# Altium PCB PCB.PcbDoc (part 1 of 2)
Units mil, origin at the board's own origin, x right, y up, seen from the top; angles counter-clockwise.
Board outline 3920 x 1470 mil, 2 copper layers (Top Layer, Bottom Layer), stack 60.433 mil thick; 97 components, 79 nets, 353 pads, 374 vias.
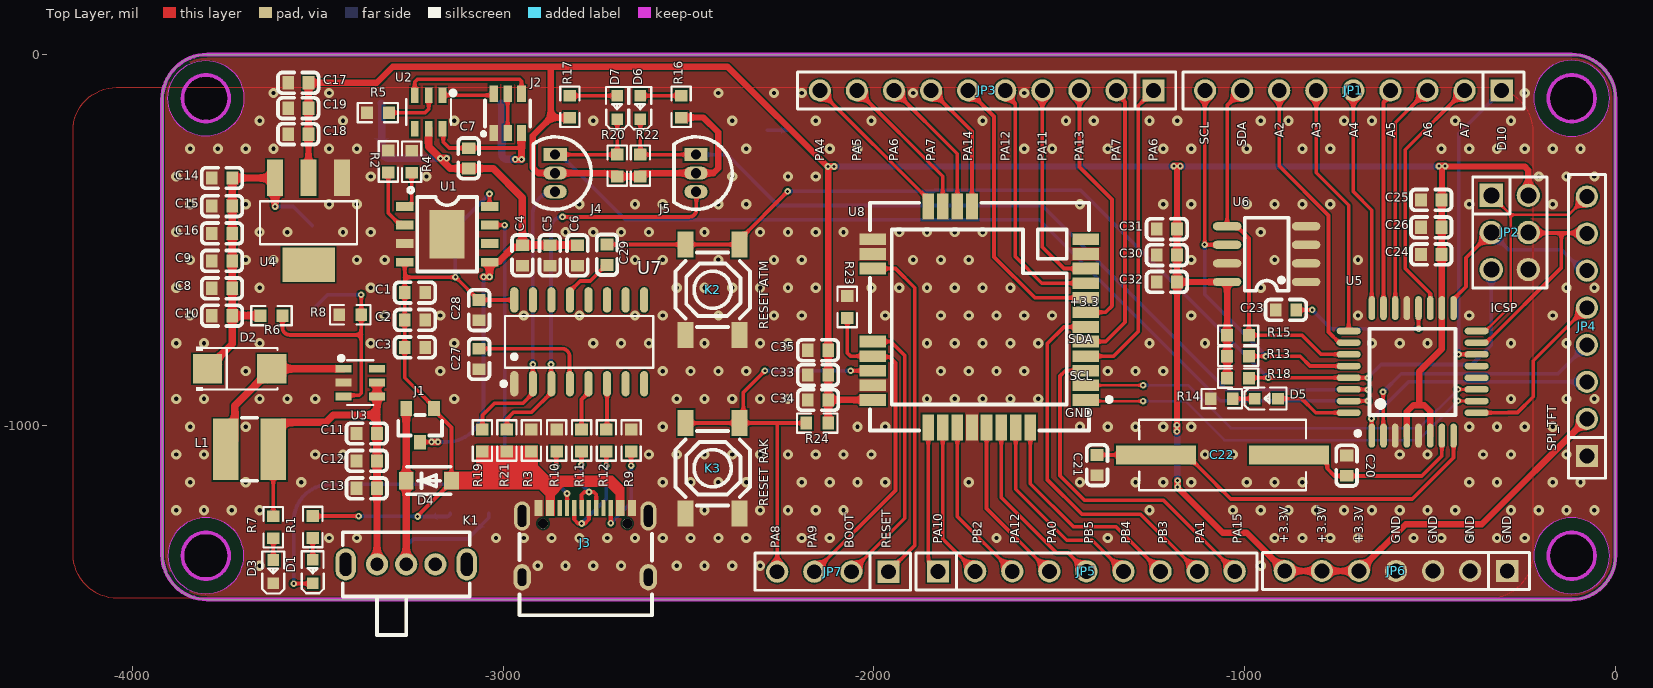
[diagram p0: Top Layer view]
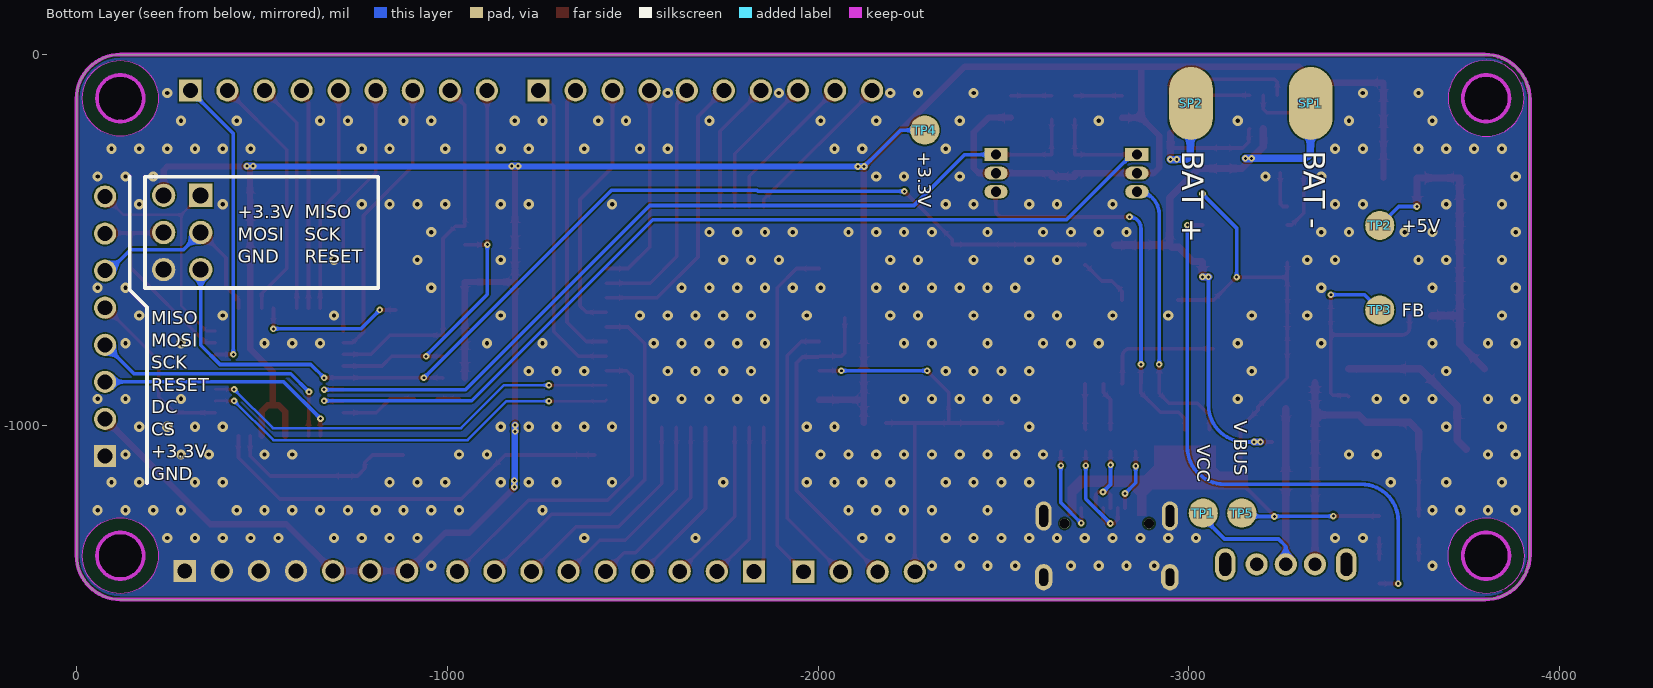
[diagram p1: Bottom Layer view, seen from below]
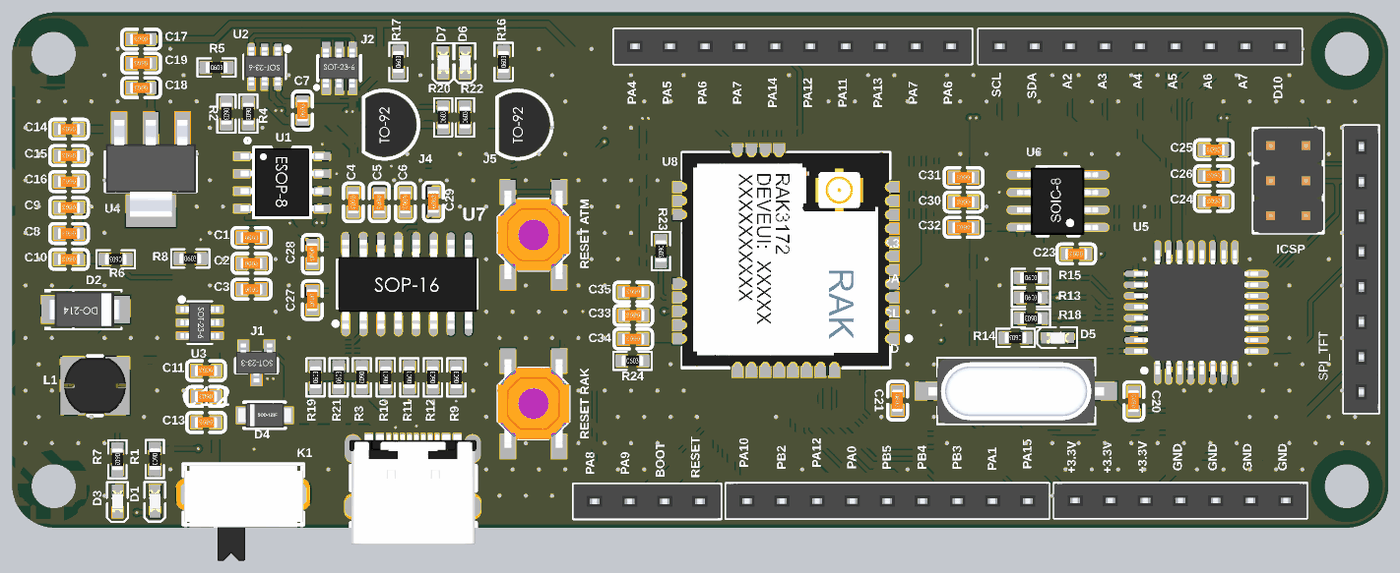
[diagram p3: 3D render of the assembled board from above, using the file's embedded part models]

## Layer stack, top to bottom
Top Solder: solder mask 0.5, Solder Resist, Dk 3.8
Top Layer: signal copper 1.378
Dielectric 1: prepreg 7.874, 7628, Dk 4.6
Core: core 41.929, FR-4, Dk 4.5
Dielectric 2: prepreg 7.874, 7628, Dk 4.6
Bottom Layer: signal copper 1.378
Bottom Solder: solder mask 0.5, Solder Resist, Dk 3.8

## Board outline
-3920,-1348.7 ccw(c-3798.7,-1348.7) -3798.7,-1470 -118.5,-1470 ccw(c-118.5,-1351.5) 0,-1351.5 0,-118.5 ccw(c-118.5,-118.5) -118.5,0 -3798.44,0 ccw(c-3798.44,-121.56) -3920,-121.56
cut-out: -181.1,-118.11 ccw(c-118.11,-118.11) -118.11,-181.1 ccw(c-118.11,-118.11) -55.12,-118.11 ccw(c-118.11,-118.11) -118.11,-55.12 ccw(c-118.11,-118.11)
cut-out: -3801.89,-181.1 cw(c-3801.89,-118.11) -3864.88,-118.11 cw(c-3801.89,-118.11) -3801.89,-55.12 cw(c-3801.89,-118.11) -3738.9,-118.11 cw(c-3801.89,-118.11)
cut-out: -3864.88,-1351.89 ccw(c-3801.89,-1351.89) -3801.89,-1414.88 ccw(c-3801.89,-1351.89) -3738.9,-1351.89 ccw(c-3801.89,-1351.89) -3801.89,-1288.9 ccw(c-3801.89,-1351.89)
cut-out: -181.1,-1351.89 ccw(c-118.11,-1351.89) -118.11,-1414.88 ccw(c-118.11,-1351.89) -55.12,-1351.89 ccw(c-118.11,-1351.89) -118.11,-1288.9 ccw(c-118.11,-1351.89)

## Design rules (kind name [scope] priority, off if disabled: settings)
BoardOutlineClearance [All] p1: gap=7.87 ignorepadtopadclearanceinfootprint=FALSE
Clearance Clearance_1 [InNet('No Net') vs InNet('No Net')] p1: gap=10 ignorepadtopadclearanceinfootprint=FALSE
Clearance [All] p2: gap=4 ignorepadtopadclearanceinfootprint=FALSE except(5: Arc-Via Track-Via SMDPad-Via THPad-Via Via-Via Via-Fill Via-Poly Via-Region)
ComponentClearance [All] p1: gap=4 collisioncheckmode=3 verticalgap=4 showdistances=TRUE
DiffPairsRouting [All] p1: maxlimit=4 minlimit=4 mostfreqgap=4 toplayer_minwidth=4 toplayer_maxwidth=71497.94 toplayer_prefwidth=4 bottomlayer_minwidth=4 bottomlayer_maxwidth=71497.94 bottomlayer_prefwidth=4 maxuncoupledlength=500
Height [All] p1: minheight=0 maxheight=71497.94 prefheight=500
HoleSize [All] p1: absolutevalues=TRUE maxlimit=248.03 minlimit=7.87 maxpercent=80.000 minpercent=20.000
HoleToHoleClearance [All] p1: gap=9.84 allowstackedmicrovias=FALSE
MinimumAnnularRing [All] p1: minimumring=3
MinimumSolderMaskSliver [All] p1: minsoldermaskwidth=0
PlaneClearance [All] p1: clearance=4
PlaneConnect PlaneConnectPowerPads [InPadClass('PowerPads')] p1: planeconnectstyle=Direct reliefexpansion=20 reliefentries=4 reliefconductorwidth=10 reliefairgap=10
PlaneConnect [All] p2: pad.planeconnectstyle=Relief pad.reliefexpansion=11.81 pad.reliefentries=4 pad.reliefconductorwidth=4 pad.reliefairgap=4 via.planeconnectstyle=Direct via.reliefexpansion=11.81 via.reliefentries=4 via.reliefconductorwidth=5 via.reliefairgap=5
PolygonConnect PolygonConnectPowerPads [All vs (InPadClass('PowerPads'))] p1: connectstyle=Direct reliefconductorwidth=10 reliefentries=4 polygonreliefangle="90 Angle" airgapwidth=10
PolygonConnect [All] p2: connectstyle=Direct reliefconductorwidth=4 reliefentries=4 polygonreliefangle="90 Angle" airgapwidth=4
RoutingVias [All] p1: holewidth=7.87 width=17.72 viastyle="Through Hole" minholewidth=7.87 minwidth=17.72 maxholewidth=248.03 maxwidth=257.87
SilkToSilkClearance [All] p1: silktosilkclearance=0
SilkToSolderMaskClearance [IsPad] p1: minsilkscreentomaskgap=4 clearancetoexposedcopper=TRUE
SolderMaskExpansion [All] p1: expansion=2.95 istentingtop=FALSE
Width [All] p1: maxlimit=71497.94 minlimit=4 preferedwidth=4
20 further rules are at their usual default settings.

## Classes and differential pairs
component class "Voltage Source": C1 C2 C3 C4 C5 C6 C7 C8 C9 C10 C11 C12 C13 C14 C15 C16 C17 C18 C19 D1 D2 D3 D4 J1 J2 J3 K1 L1 R1 R2 R3 R4 R5 R6 R7 R8 R9 R10 R11 R12 SP1 SP2 TP1 TP2 TP3 TP4 TP5 U1 U2 U3 U4
component class Peripheral: C27 C28 C29 C30 C31 C32 C33 C34 C35 J4 J5 K3 R19 R20 R21 R22 R23 R24 Reset_U4 U6 U7 U8
component class "Micro Controller": C20 C21 C22 C23 C24 C25 C26 D5 D6 D7 K2 R13 R14 R15 R16 R17 R18 Reset_U4 U5
component class Connector: JP1 JP2 JP3 JP4 JP5 JP6 JP7
differential pair D: +D_P -D_N

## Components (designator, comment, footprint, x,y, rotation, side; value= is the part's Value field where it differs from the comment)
C1 "100nF" C0603 -3238.19,-642.03 r0 top
C2 "10uF" C0603 -3238.19,-715.94 r0 top
C3 "22uF" C0603 -3238.19,-789.85 r0 top
C4 "100nF" C0603 -2948.12,-541.81 r270 top
C5 "10uF" C0603 -2874.21,-541.81 r270 top
C6 "22uF" C0603 -2800.07,-541.81 r270 top
C7 "100nF" C0603 -3093,-280 r90 top
C8 "100nF" C0603 -3758.31,-630.54 r180 top
C9 "10uF" C0603 -3758.31,-556.63 r180 top
C10 "22uF" C0603 -3758.31,-704.46 r180 top
C11 "100nF" C0603 -3367.87,-1022.15 r180 top
C12 "10uF" C0603 -3367.87,-1096.06 r180 top
C13 "22uF" C0603 -3367.87,-1169.97 r180 top
C14 "100nF" C0603 -3758.31,-333.07 r180 top
C15 "10uF" C0603 -3758.31,-408.76 r180 top
C16 "22uF" C0603 -3758.31,-482.67 r180 top
C17 "100nF" C0603 -3552.56,-76.27 r180 top
C18 "10uF" C0603 -3552.56,-214.94 r180 top
C19 "22uF" C0603 -3552.56,-144.94 r180 top
C20 "12pF" C0603 -725,-1109 r90 top
C21 "12pF" C0603 -1398,-1107.56 r270 top
C22 "X49SM16MSD2SC" X49SM16MSD2SC -1060,-1080 r0 top
C23 "100nF" C0603 -889,-689 r180 top
C24 "100nF" C0603 -497,-539.25 r180 top
C25 "10uF" C0603 -497,-392 r180 top
C26 "22uF" C0603 -497,-466 r180 top
C27 "100nF" C0603 -3065,-821 r270 top
C28 "100nF" C0603 -3065,-689.47 r270 top
C29 "100nF" C0603 -2720,-540 r90 top
C30 "100nF" C0603 -1210,-541 r180 top
C31 "10uF" C0603 -1210,-471 r180 top
C32 "22uF" C0603 -1210,-613.41 r180 top
C33 "100nF" C0603 -2150.81,-864.55 r180 top
C34 "10uF" C0603 -2151,-931.66 r180 top
C35 "22uF" C0603 -2151,-797.66 r180 top
D1 "RED" LED0603 -3513.54,-1394.46 r90 top
D2 "SS34" SS34 -3711,-847.6 r0 top
D3 "YELLOW" LED0603 -3620,-1395 r90 top
D4 "SOD4007" SOD4007 -3200.55,-1149.37 r0 top
D5 "YELLOW" LED0603 -941.73,-928.25 r0 top
D6 "YELLOW" LED0603 -2630.14,-142.82 r90 top
D7 "YELLOW" LED0603 -2692.55,-142.82 r90 top
J1 "AO3401A" AO3401A -3224.17,-1000 r90 top
J2 "FS8205A" FS8205A -2988,-159 r270 top
J3 "TYPE-C 16PIN 2MD(073)" TYPE_C_FAMALE -2778.78,-1316.37 r0 top
J4 "2N7000" 2N7000 -2860,-320 r270 top
J5 "2N7000" 2N7000 -2480,-320 r270 top
JP1 "JP 1x9 2.54" "JP 1x9 CT" -707,-97 r180 top
JP2 "Header" "JP 2x3 DT" -285,-480 r270 top
JP3 "Header" "JP 1x10 CT" -1245.91,-97.02 r180 top
JP4 "JP 1x8 2.54" "JP 1x8 CT" -77,-1083 r90 top
JP5 "JP 1x9 2.54" "JP 1x9 CT" -1427,-1394 r0 top
JP6 "JP 1x7 2.54" "JP 1x7 CT" -292,-1393 r180 top
JP7 "JP 1x4 2.54" "JP 1x4 CT" -1961,-1395 r180 top
K1 "SK12D07VG4" SK12D07VG4 -3261.58,-1375 r0 top
K2 "TS-1140SP-4x4x1.5-260" 4x4x1.5 -2435,-634.49 r90 top
K3 "TS-1140SP-4x4x1.5-260" 4x4x1.5 -2435,-1116.05 r90 top
L1 "220uH" CD43 -3684.12,-1065 r270 top
R1 "1kΩ" R0603 -3513.68,-1274.46 r270 top
R2 "2kΩ" R0603 -3309.81,-288.78 r270 top
R3 "10kΩ" R0603 -2924,-1041 r270 top
R4 "1kΩ" R0603 -3247,-289 r270 top
R5 "1kΩ" R0603 -3338,-157 r0 top
R6 "5k1" R0603 -3625,-704.46 r180 top
R7 "1kΩ" R0603 -3620.14,-1275 r270 top
R8 "680" R0603 -3412.66,-702 r0 top
R9 "5k1Ω" R0603 -2654.87,-1041.22 r90 top
R10 "5k1Ω" R0603 -2855.98,-1041.22 r90 top
R11 "0Ω" R0603 -2788.73,-1041.22 r90 top
R12 "0Ω" R0603 -2721.8,-1041.22 r90 top
R13 "4k7Ω" R0603 -1017.84,-813.78 r0 top
R14 "1kΩ" R0603 -1061.73,-928.25 r180 top
R15 "4k7Ω" R0603 -1017.84,-757.23 r0 top
R16 "1kΩ" R0603 -2520,-141 r90 top
R17 "1kΩ" R0603 -2820,-141 r90 top
R18 "10kΩ" R0603 -1017.84,-872.78 r180 top
R19 "10kΩ" R0603 -3056,-1041 r90 top
R20 "10kΩ" R0603 -2692.41,-299.66 r90 top
R21 "10kΩ" R0603 -2990,-1041 r90 top
R22 "10kΩ" R0603 -2630,-299.66 r90 top
R23 "10kΩ" R0603 -2072,-681 r270 top
R24 "10kΩ" R0603 -2153.1,-994 r0 top
SP1 "BAT+" SP -3329,-132 r0 top
SP2 "BAT-" SP -3006,-132 r180 top
TP1 "TP" TP -3039,-1237 r0 top
TP2 "TP" TP -3515,-461 r0 top
TP3 "TP" TP -3515,-689 r0 top
TP4 "TP" TP -2288,-204 r0 top
TP5 "TP" TP -3143,-1237 r0 top
U1 "TP4056" TP4056 -3151.25,-485 r270 top
U2 "DW01A" DW01A -3201,-155 r180 top
U3 "MT3608" MT3608 -3385.55,-885 r270 top
U4 "LM1117S-3.3" AMS1117-3.3 -3525,-450 r90 top
U5 "ATMEGA328-AU" ATMEGA328-AU -547,-856 r0 top
U6 "AT24C02C-SSHM-T" AT24C02C-SSHM-T -941,-538.41 r90 top
U7 "CH340C" CH340C -2795,-775 r0 top
U8 "RAK3172-9-SM-I" RAK3172-9-SM-I -1716,-708 r180 top

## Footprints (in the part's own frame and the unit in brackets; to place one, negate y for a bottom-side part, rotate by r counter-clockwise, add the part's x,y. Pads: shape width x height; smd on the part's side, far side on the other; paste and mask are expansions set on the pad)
2N7000 [mm]
  rect 0.9x1.6 hole 0.7 paste-2539.97 mask+0.051: 1(-1.27,0)
  oval 0.9x1.6 hole 0.7 paste-2539.97 mask+0.051: 2(0,0) 3(1.27,0)
  silkscreen extent -2.48,-1.5 2.48,2.48, body extent -2.3,-1.3 2.3,2.3, height 5.6
4x4x1.5 [mm]
  rect 1.8x1.1 smd paste+0 mask+0.051: 1(-3.1,1.85) 2(3.1,1.85) 3(-3.1,-1.85) 4(3.1,-1.85)
  silkscreen extent -2.55,-2.55 2.55,2.55, body extent -3.2,-2.6 3.2,2.6, height 1.5
AMS1117-3.3 [mm]
  rect 2.5x1.1 smd paste+0 mask+0.051: 1(2.97,-2.3) 2(2.97,0) 3(2.97,2.3)
  rect 2.34x3.6 smd paste+0 mask+0.051: 4(-2.97,0)
  silkscreen extent -1.57,-3.33 1.37,3.33, body extent -3.37,-3.25 3.63,3.25, height 1.8
AO3401A [mm]
  rect 1x0.8 smd paste+0 mask+0.051: 1(1.15,-0.95) 2(1.15,0.95) 3(-1.15,0)
  silkscreen extent -0.7,-1.5 0.7,1.5, body extent -1.4,-1.45 1.4,1.45, height 1.26
AT24C02C-SSHM-T [mil]
  oval 22.38x76.78 smd paste+0 mask+2: 1(-75,-106.5) 2(-25,-106.5) 3(25,-106.5) 4(75,-106.5) 5(75,106.5) 6(25,106.5) 7(-25,106.5) 8(-75,106.5)
  silkscreen extent -98,-59 98,59, body extent -96,-115 96,117, height 60
ATMEGA328-AU [mm]
  oval 0.45x1.65 smd paste+0 mask+0.051: 1(-2.8,-4.369) 2(-2,-4.369) 3(-1.2,-4.369) 4(-0.4,-4.369) 5(0.4,-4.369) 6(1.2,-4.369) 7(2,-4.369) 8(2.8,-4.369) 17(2.8,4.369) 18(2,4.369) 19(1.2,4.369) 20(0.4,4.369) 21(-0.4,4.369) 22(-1.2,4.369) 23(-2,4.369) 24(-2.8,4.369)
  oval 1.65x0.45 smd paste+0 mask+0.051: 9(4.382,-2.8) 10(4.382,-2) 11(4.382,-1.2) 12(4.382,-0.4) 13(4.382,0.4) 14(4.382,1.2) 15(4.382,2) 16(4.382,2.8) 25(-4.381,2.8) 26(-4.381,2) 27(-4.381,1.2) 28(-4.381,0.4) 29(-4.381,-0.4) 30(-4.381,-1.2) 31(-4.381,-2) 32(-4.381,-2.8)
  silkscreen extent -3.91,-4.36 2.94,2.95, body extent -4.5,-4.5 4.5,4.5, height 1.05
C0603 [mm]
  rect 0.8x0.9 smd: 1(-0.7,0) 2(0.7,0)
  silkscreen extent -1.39,-0.71 1.39,0.71, body extent -0.8,-0.4 0.8,0.4, height 0.4
CD43 [mm]
  rect 4.2x1.75 smd paste+0 mask+0.051: 1(0,1.625) 2(0,-1.625)
  silkscreen extent -2.16,-0.52 2.16,0.52, body extent -2,-2.25 2,2.25, height 3.22
CH340C [mm]
  oval 0.56x1.745 smd paste+0 mask+0.051: 1(-4.445,-2.873) 2(-3.175,-2.873) 3(-1.905,-2.873) 4(-0.635,-2.873) 5(0.635,-2.873) 6(1.905,-2.873) 7(3.175,-2.873) 8(4.445,-2.873) 9(4.445,2.873) 10(3.175,2.873) 11(1.905,2.873) 12(0.635,2.873) 13(-0.635,2.873) 14(-1.905,2.873) 15(-3.175,2.873) 16(-4.445,2.873)
  silkscreen extent -5.33,-3.02 5.08,1.77, body extent -4.95,-3.26 5.05,3.2, height 1.92
DW01A [mm]
  rect 0.532x1.072 smd paste+0 mask+0.051: 1(-0.95,-1.149) 2(0,-1.149) 3(0.95,-1.149) 4(0.95,1.149) 5(0,1.149) 6(-0.95,1.149)
  silkscreen extent -1.82,-1.45 1.54,0.89, body extent -1.45,-1.43 1.45,1.37, height 1.46
FS8205A [mm]
  rect 1.1x0.6 smd paste+0 mask+0.051: 1(1.35,-0.95) 2(1.35,0) 3(1.35,0.95) 4(-1.35,0.95) 5(-1.35,0) 6(-1.35,-0.95)
  silkscreen extent -0.9,-1.78 1.52,1.55, body extent -1.4,-1.48 1.4,1.42, height 1.46
"JP 1x4 CT" [mm]
  rect 1.52x1.52 hole 1.02: 1(0,0)
  round 1.52 hole 1.02: 2(2.54,0) 3(5.08,0) 4(7.62,0)
  silkscreen extent -1.52,-1.27 9.14,1.27, body extent -1.52,-1.25 9.14,1.25, height 8.51
"JP 1x7 CT" [mm] "7 row, straight, gold plating"
  rect 1.52x1.52 hole 1.02: 1(0,0)
  round 1.52 hole 1.02: 2(2.54,0) 3(5.08,0) 4(7.62,0) 5(10.16,0) 6(12.7,0) 7(15.24,0)
  silkscreen extent -1.52,-1.27 16.76,1.27, body extent -1.52,-1.25 16.76,1.25, height 8.51
"JP 1x8 CT" [mm] "8 row, straight, gold plating"
  rect 1.52x1.52 hole 1.02: 1(0,0)
  round 1.52 hole 1.02: 2(2.54,0) 3(5.08,0) 4(7.62,0) 5(10.16,0) 6(12.7,0) 7(15.24,0) 8(17.78,0)
  silkscreen extent -1.52,-1.27 19.3,1.27, body extent -1.52,-1.25 19.3,1.25, height 8.51
"JP 1x9 CT" [mm] "9 row, straight, gold plating"
  rect 1.52x1.52 hole 1.02: 1(-10.16,0)
  round 1.52 hole 1.02: 2(-7.62,0) 3(-5.08,0) 4(-2.54,0) 5(0,0) 6(2.54,0) 7(5.08,0) 8(7.62,0) 9(10.16,0)
  silkscreen extent -11.68,-1.27 11.68,1.27, body extent -11.68,-1.25 11.68,1.25, height 8.51
"JP 1x10 CT" [mm] "10 row, straight, gold plating"
  rect 1.52x1.52 hole 1.02: 1(0,0)
  round 1.52 hole 1.02: 2(2.54,0) 3(5.08,0) 4(7.62,0) 5(10.16,0) 6(12.7,0) 7(15.24,0) 8(17.78,0) 9(20.32,0) 10(22.86,0)
  silkscreen extent -1.52,-1.27 24.38,1.27, body extent -1.52,-1.25 24.38,1.25, height 8.51
"JP 2x3 DT" [mm]
  rect 1.6x1.6 hole 1.1: 1(-2.54,-1.27)
  round 1.6 hole 1.1: 2(0,-1.27) 3(2.54,-1.27) 4(2.54,1.27) 5(0,1.27) 6(-2.54,1.27)
  silkscreen extent -3.81,-2.54 3.81,2.54, body extent -3.81,-2.54 3.81,2.54, height 8.55
LED0603 [mm]
  rect 0.8x0.8 smd paste+0 mask+0.051: 1(-0.799,-0.004) 2(0.799,0.004)
  silkscreen extent -1.49,-0.75 1.39,0.76, body extent -0.8,-0.42 0.8,0.38, height 0.7
MT3608 [mm]
  rect 0.532x1.072 smd paste+0 mask+0.051: 1(-0.95,-1.149) 2(0,-1.149) 3(0.95,-1.149) 4(0.95,1.149) 5(0,1.149) 6(-0.95,1.149)
  silkscreen extent -1.82,-1.45 1.54,0.89, body extent -1.45,-1.4 1.45,1.4, height 1.46
R0603 [mil]
  rect 31.75x34.02 smd paste-3937.01 mask+2: 1(-29.66,0) 2(29.66,0)
  silkscreen extent -55,-26 55,26, body extent -31,-16 31,16, height 18
RAK3172-9-SM-I [mm]
  rect 1.8x0.8 smd paste+0 mask+0.051: 1(-7.287,5.68) 2(-7.287,4.68) 3(-7.287,3.68) 4(-7.287,2.68) 5(-7.287,1.68) 6(-7.287,0.68) 7(-7.287,-0.32) 8(-7.287,-1.32) 9(-7.287,-2.32) 10(-7.287,-3.32) 11(-7.287,-4.32) 12(-7.287,-5.32) 17(7.287,-5.32) 18(7.287,-4.32) 19(7.287,-3.32) 20(7.287,1.68) 21(7.287,2.68) 22(7.287,3.68) 23(7.287,4.68) 24(7.287,5.68)
  rect 0.8x1.8 smd paste+0 mask+0.051: 13(0.5,-7.569) 14(1.5,-7.569) 15(2.5,-7.569) 16(3.5,-7.569) 25(3.5,7.569) 26(2.5,7.569) 27(1.5,7.569) 28(0.5,7.569) 29(-0.5,7.569) 30(-1.5,7.569) 31(-2.5,7.569) 32(-3.5,7.569)
  silkscreen extent -9.05,-7.82 7.49,7.78, body extent -7.5,-7.82 7.49,7.67, height 3.51
SK12D07VG4 [mil]
  round 60 hole 36 paste-99999 mask+1.97: 1(-78.74,0) 2(0,0) 3(78.74,0)
  oval 55.12x86.61 hole 31.5 slot 62.99 at 90 deg paste-99999 mask+1.97: 4(163.39,0) 5(-163.39,0)
  silkscreen extent -171,-191 171,87, body extent -169,-190 170,83, height 188
SOD4007 [mm]
  rect 1x1.2 smd paste+0 mask+0.051: 1(-1.55,0) 2(1.55,0)
  silkscreen extent -1.52,-0.93 1.49,0.95, body extent -1.9,-0.9 1.9,0.9, height 1.02
SP [mm]
  oval 3x5 smd far side paste+0 mask+0.051: 1(0,0)
SS34 [mm]
  rect 2x2 smd paste+0 mask+0.051: 1(-2.2,0) 2(2.2,0)
  silkscreen extent -2.98,-1.5 2.6,1.5, body extent -2.65,-1.29 2.49,1.27, height 2.63
TP [mm]
  round 2 smd far side paste+0 mask+0.051: 1(0,0)
TP4056 [mm]
  rect 0.6x1.2 smd paste+0 mask+0.051: 1(-1.905,-2.908) 2(-0.635,-2.908) 3(0.635,-2.908) 4(1.905,-2.908) 5(1.905,2.908) 6(0.635,2.908) 7(-0.635,2.908) 8(-1.905,2.908)
  rect 3.3x2.4 smd paste+0 mask+0.051: 9(0,0)
  silkscreen extent -3.2,-2.67 2.55,2.05, body extent -2.46,-3 2.44,3, height 1.76
TYPE_C_FAMALE [mm]
  rect 0.55x1.1 smd paste-100 mask+0.05: 1(-3.2,2.375) 2(-2.4,2.375) 11(2.4,2.375) 12(3.2,2.375)
  rect 0.3x1.1 smd paste-100 mask+0.05: 3(-1.75,2.375) 4(-1.25,2.375) 5(-0.75,2.375) 6(-0.25,2.375) 7(0.25,2.375) 8(0.75,2.375) 9(1.25,2.375) 10(1.75,2.375)
  oval 1.2x1.8 hole 0.6 slot 1.2 at 90 deg paste-2539.97 mask+0.05: 13(-4.325,-2.375) 14(4.325,-2.375)
  oval 1.1x2 hole 0.6 slot 1.5 at 90 deg paste-2539.97 mask+0.05: 13(-4.325,1.825) 14(4.325,1.825)
  round 0.7 hole 0.7 unplated paste-2539.97: ""(-2.89,1.305) ""(2.89,1.305)
  silkscreen extent -4.5,-4.97 4.57,0.6, body extent -4.57,-5.09 4.63,2.86, height 3.21
X49SM16MSD2SC [mm]
  rect 5.5x1.3 smd paste+0 mask+0.051: 1(-4.553,0) 2(4.553,0)
  silkscreen extent -5.71,-2.41 5.72,2.41, body extent -6.35,-2.38 6.35,2.32, height 4.2

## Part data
C1 C4 C7 C8 C11 C14 C17 C23 C24 C27 C28 C29 C30 C33: library part C0603_100nF_±1%, "50V 10pF NP0 ±1% 0402 Multilayer Ceramic Capacitors MLCC - SMD/SMT ROHS", LCSC Part #=C513681, Manufacturer=YAGEO, Mfr. Part #=CC0402FRNPO9BN100, Package=0603, Tolerance=±1%, Voltage Rating=50V
C2 C5 C9 C12 C15 C18 C25 C31 C34: library part C0603_10uF_±1%, "50V 10pF NP0 ±1% 0402 Multilayer Ceramic Capacitors MLCC - SMD/SMT ROHS", LCSC Part #=C513681, Manufacturer=YAGEO, Mfr. Part #=CC0402FRNPO9BN100, Package=0603, Tolerance=±1%, Voltage Rating=50V
C3 C6 C10 C13 C16 C19 C26 C32 C35: library part C0603_22uF_±1%, "50V 10pF NP0 ±1% 0402 Multilayer Ceramic Capacitors MLCC - SMD/SMT ROHS", LCSC Part #=C513681, Manufacturer=YAGEO, Mfr. Part #=CC0402FRNPO9BN100, Package=0603, Tolerance=±1%, Voltage Rating=50V
C20 C21: library part C0603_12pF_±1%, "50V 10pF NP0 ±1% 0402 Multilayer Ceramic Capacitors MLCC - SMD/SMT ROHS", LCSC Part #=C513681, Manufacturer=YAGEO, Mfr. Part #=CC0402FRNPO9BN100, Package=0603, Tolerance=±1%, Voltage Rating=50V
C22: "16MHz Crystal Oscillator 20pF ±20ppm ±30ppm HC-49S-SMD Crystals ROHS", LCSC Part #=C12676, Load Capacitance=20pF, Manufacturer="YXC Crystal Oscillators", Package=HC-49S-SMD
D1: library part D0603_RED, "25mcd~40mcd Water Clear -40℃~+85℃ 624nm Red 120° 60mW 0402 LED Indication - Discrete ROHS", LCSC Part #=C965793, Manufacturer=XINGLIGHT, Mfr. Part #=XL-1005UGC, Package=0603, Power(Watts)=60mW, Voltage - Forward(Vf)=3V
D2: "40V Independent 3A 550mV@3A SMA(DO-214AC) Schottky Diodes ROHS", Current - Rectified=3A, LCSC Part #=C8678, Manufacturer="MDD(Microdiode Semiconductor)", Package=SMA(DO-214AC), Voltage - DC Reverse(Vr)=40V
D3 D5 D6 D7: library part D0603_YELLOW, "25mcd~40mcd Water Clear -40℃~+85℃ 624nm Red 120° 60mW 0402 LED Indication - Discrete ROHS", LCSC Part #=C965793, Manufacturer=XINGLIGHT, Mfr. Part #=XL-1005UGC, Package=0603, Power(Watts)=60mW, Voltage - Forward(Vf)=3V
D4: "1A Independent 1kV 1.1V@1A SOD-123FL Diodes - General Purpose ROHS", Current - Rectified=1A, LCSC Part #=C18124, Manufacturer="MDD(Microdiode Semiconductor)", Package=SOD-123FL, Voltage - DC Reverse(Vr)=1kV
J1: library part AO3401, "30V 4A 900mV@250uA 1 P-Channel SOT-23 MOSFETs ROHS", Current - Continuous Drain(Id)=4A, Drain to Source Voltage=30V, LCSC Part #=C15127, Manufacturer=AOS, Package=SOT-23
J2: "20V 9A 31.5mΩ@2.5V 1.5W 1.2V@250uA SOT-23-6 MOSFETs ROHS", Current - Continuous Drain(Id)=9A, Drain to Source Voltage=20V, LCSC Part #=C2830320, Manufacturer="TECH PUBLIC", Package=SOT-23-6
J3: library part TYPE_C_FAMALE_16PIN, "3A 1 Surface Mount, Right Angle 16P Female -25℃~+85℃ Type-C SMD USB Connectors ROHS", LCSC Part #=C2765186, Manufacturer="SHOU HAN", Package=SMD
J4 J5: "60V 200mA 400mW 5Ω@10V 3V@1mA 1 N-Channel TO-92-3L MOSFETs ROHS", Current - Continuous Drain(Id)=200mA, Drain to Source Voltage=60V, Gate Threshold Voltage (Vgs(th))=3V@1mA, LCSC Part #=C232838, Manufacturer=onsemi, Package=TO-92-3L
JP1 JP5: library part "JP 1x9 2.54 Cai Thang", "Cắm"
JP2: library part "JP 2x3 2.54 Duc Thang", "Cắm"
JP3: library part "JP 1x10 2.54 Cai Thang", "Cắm"
JP4: library part "JP 1x8 2.54 Cai Thang", "Cắm"
JP6: library part "JP 1x7 2.54 Cai Thang", "Cắm"
JP7: library part "JP 1x4 2.54 Cai Thang", "Cắm"
K1: "500mA SPDT 50V 5,000 Cycles Through Hole Slide Switches ROHS", LCSC Part #=C393937, Manufacturer="SHOU HAN", Package="Through Hole"
K2 K3: "SMD Tactile Switches ROHS", LCSC Part #=C49023394, Manufacturer=CAX, Package=SMD
L1: library part CD4-220UH, "360mA 220uH ±20% SMD,4.5x4x3.2mm Power Inductors ROHS", Current Rating=360mA, DC Resistance(DCR)=3.4Ω, LCSC Part #=C492283, Manufacturer=YJYCOIN, Mfr. Part #=CD43YP0403-221M, Package=SMD,4.5x4x3.2mm, Tolerance=±20%
R1 R4 R5 R7 R14 R16 R17: library part R0603_1kΩ_±1%, "62.5mW Thick Film Resistor 50V ±1% ±200ppm/℃ 10Ω 0402 Chip Resistor - Surface Mount ROHS", LCSC Part #=C138066, Manufacturer=YAGEO, Mfr. Part #=RC0402FR-0710RL, Package=0603, Tolerance=±1%
R2: library part R0603_2kΩ_±1%, "62.5mW Thick Film Resistor 50V ±1% ±200ppm/℃ 10Ω 0402 Chip Resistor - Surface Mount ROHS", LCSC Part #=C138066, Manufacturer=YAGEO, Mfr. Part #=RC0402FR-0710RL, Package=0603, Tolerance=±1%
R3 R18 R19 R20 R21 R22 R23 R24: library part R0603_10kΩ_±1%, "62.5mW Thick Film Resistor 50V ±1% ±200ppm/℃ 10Ω 0402 Chip Resistor - Surface Mount ROHS", LCSC Part #=C138066, Manufacturer=YAGEO, Mfr. Part #=RC0402FR-0710RL, Package=0603, Tolerance=±1%
R6: library part R0603_10kΩ_±1%, "62.5mW Thick Film Resistor 50V ±1% ±200ppm/℃ 10Ω 0402 Chip Resistor - Surface Mount ROHS", LCSC Part #=C138066, Manufacturer=YAGEO, Mfr. Part #=RC0402FR-0710RL, Package=0603, Resistance=10kΩ, Tolerance=±1%
R8: library part R0603_2kΩ_±1%, "62.5mW Thick Film Resistor 50V ±1% ±200ppm/℃ 10Ω 0402 Chip Resistor - Surface Mount ROHS", LCSC Part #=C138066, Manufacturer=YAGEO, Mfr. Part #=RC0402FR-0710RL, Package=0603, Resistance=2kΩ, Tolerance=±1%
R9 R10: library part R0603_5k1Ω_±1%, "100mW Thick Film Resistor 75V ±100ppm/℃ ±1% 5.1kΩ 0603 Chip Resistor - Surface Mount ROHS", LCSC Part #=C2907044, Manufacturer=FOJAN, Mfr. Part #=FRC0603F5101TS, Package=0603, Tolerance=±1%
R11 R12: library part R0603_0Ω_±5%, "100mW Thick Film Resistor 75V ±5% 0Ω 0603 Chip Resistor - Surface Mount ROHS", LCSC Part #=C95177, Manufacturer=YAGEO, Mfr. Part #=RC0603JR-070RL, Package=0603, Tolerance=±5%
R13 R15: library part R0603_4k7Ω_±1%, "62.5mW Thick Film Resistor 50V ±1% ±200ppm/℃ 10Ω 0402 Chip Resistor - Surface Mount ROHS", LCSC Part #=C138066, Manufacturer=YAGEO, Mfr. Part #=RC0402FR-0710RL, Package=0603, Tolerance=±1%
SP1 SP2: library part SP
U1: "4V~6V Lithium-ion/Polymer 1 ESOP-8 Battery Management ROHS", Charging Saturation Voltage=4.2V, LCSC Part #=C382139, Manufacturer=TPOWER, Package=ESOP-8, Voltage - Supply=4V~6V
U2: "1.5V~8V Lithium-ion/Polymer 1 SOT-23-6 Battery Management ROHS", Charging Saturation Voltage=4.3V, LCSC Part #=C2927799, Manufacturer=YONGYUTAI, Package=SOT-23-6, Voltage - Supply=1.5V~8V
U3: "Boost Adjustable 2A 2V~24V SOT-23-6 DC-DC Converters ROHS", Frequency - Switching=1.2MHz, LCSC Part #=C84817, Manufacturer="XI'AN Aerosemi Tech", Package=SOT-23-6
U4: "75dB@(120Hz) 1A Fixed 3.3V Positive 12V SOT-223-3 Voltage Regulators - Linear, Low Drop Out (LDO) Regulators ROHS", LCSC Part #=C126027, Manufacturer=HTC, Output Current=1A, Package=SOT-223-3, Voltage - Supply=12V
U5: "AVR 20MHz TQFP-32(7x7) Microcontrollers (MCU/MPU/SOC) ROHS", LCSC Part #=C618731, Manufacturer=MICROCHIP, Package=TQFP-32(7x7), Voltage - Supply=1.8V~5.5V
U6: "2Kbit 1MHz I2C SOIC-8 EEPROM ROHS", LCSC Part #=C6203, Manufacturer=MICROCHIP, Package=SOIC-8, Voltage - Supply=1.7V~5.5V
U7: "2Mbps Transceiver USB 2.0 SOP-16 USB Converters ROHS", LCSC Part #=C84681, Manufacturer=WCH, Package=SOP-16, Voltage - Supply=3.3V;5V
U8: "15km SMD,15.5x15mm LoRa Modules ROHS", LCSC Part #=C19723905, Manufacturer=RAKwireless, Package=SMD,15.5x15mm, Voltage - Supply=2V~3.6V

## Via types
v1: diameter 27.56, hole 11.81, Top Layer to Bottom Layer, tented both sides, 319 vias
v2: diameter 17.72, hole 7.87, Top Layer to Bottom Layer, tented both sides, 55 vias

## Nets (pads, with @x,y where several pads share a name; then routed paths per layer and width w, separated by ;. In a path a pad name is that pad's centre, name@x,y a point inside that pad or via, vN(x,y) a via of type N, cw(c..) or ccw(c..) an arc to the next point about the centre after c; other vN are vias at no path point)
+3.3: C17.1 C18.1 C19.1 C24.1 C25.1 C26.1 C30.1 C31.1 C32.1 C33.1 C34.1 C35.1 J4.2 J5.2 JP2.6 JP4.2 JP6.5 JP6.6 JP6.7 R13.1 R15.1 R16.1 R17.1 R18.2 R20.1 R22.1 R24.2 TP4.1 U4.2 U5.4 U5.6 U5.18 U6.8 U8.24 | length 9419
  Top Layer w10: v2@-2124.77,-302.28 v2(-2124.5,-302) ; v2@-1191.22,-301.28 v2(-1190.94,-301) ; v2(-1183,-1016.5) v2@-1182.73,-1016.78 ; v2(-1181,-1166.5) v2@-1180.73,-1166.78 ; v2@-476.77,-301.28 v2(-476.5,-301)
  Top Layer w17: U4.2@-3525,-333.07 C18.1@-3525,-214.94 C19.1@-3525,-144.94 C17.1@-3525,-76.27 -3341.27,-76.27 -3298,-33 -2868,-33 ; R17.1@-2820,-170.66 -2871.66,-170.66 ; R20.1@-2692.41,-329.32 R22.1@-2630,-329.32 ; R20.1@-2692.41,-320 J4.2@-2860,-320 -2905,-320 -2920,-305 -2920,-219 -2871.66,-170.66 ; R22.1@-2630,-320 J5.2@-2480,-320 -2433,-320 -2420,-307 -2420,-210 -2460,-170 -2519.34,-170 R16.1@-2520,-170.66 ; R24.2@-2123.44,-994 C34.1@-2123.44,-931.66 C35.1@-2123.44,-797.66 -2123.44,-304.56 -2395,-33 -2868,-33 ; C34.1@-2110.36,-931.55 -2002.99,-931.55 U8.24@-2002.91,-931.63 ; v2@-1182.44,-302 C31.1@-1182.44,-471 C30.1@-1182.44,-541 C32.1@-1182.44,-613.41 ; v2@-1182,-1167 -1059,-1290 -995,-1290 JP6.7@-892,-1393 JP6.6@-792,-1393 JP6.5@-692,-1393 -566,-1267 -361,-1267 JP4.2@-77,-983 ; v2@-1182,-1008 -1182,-1007.81 -1182.44,-1007.37 C32.1@-1182.44,-613.41 ; R18.2@-1047.5,-872.78 R13.1@-1047.5,-813.78 R15.1@-1047.5,-757.23 U6.8@-1047.5,-613.41 C32.1@-1182.44,-613.41 ; U5.4@-562.75,-1028 -562.75,-963.75 -545,-946 -529,-946 ; U5.6@-499.76,-1028 -499.76,-962.24 -516,-946 -529,-946 ; JP2.6@-235,-380 -235,-311.98 -244.96,-302.02 -468.02,-302.02 -468.02,-392.67 -468.4,-393.04 -468.4,-683.86 U5.18@-468.26,-684 -468.26,-794.26 -529,-855 -529,-946 ; -2871.66,-170.66 -2871.66,-36.66 -2868,-33
  Bottom Layer w10: TP4.1@-2288,-204 -2222.5,-204 v2(-2124.5,-302) -2123.5,-303 -2108.5,-303 v2(-2107.5,-302) ; v2(-1190.94,-301) -1189.94,-302 -1174.94,-302 v2(-1173.94,-301) ; v2(-1183,-1016.5) -1182,-1015.5 -1182,-1000.5 v2(-1183,-999.5) ; v2(-1181,-1166.5) -1180,-1165.5 -1180,-1150.5 v2(-1181,-1149.5) ; v2(-476.5,-301) -475.5,-302 -460.5,-302 v2(-459.5,-301)
  Bottom Layer w17: v2@-2126,-302 v2(-2124.5,-302) v2(-2107.5,-302) -1189.94,-302 v2@-468,-302 ; v2@-1182,-1167 v2@-1182,-1008
+5: C8.1 C9.1 C10.1 C14.1 C15.1 C16.1 D2.1 R6.2 TP2.1 U4.3 | length 931.8
  Top Layer w20: D2.1@-3797.62,-847.6 -3730.75,-780.73 C10.1@-3730.75,-704.46 ; R6.2@-3654.66,-704.46 C10.1@-3730.75,-704.46 ; v2(-3615,-410) -3615.55,-409.45 U4.3@-3615.55,-333.07 C14.1@-3730.75,-333.07 C15.1@-3730.75,-408.76 C16.1@-3730.75,-482.67 C9.1@-3730.75,-556.63 C8.1@-3730.75,-630.54 C10.1@-3730.75,-704.46
  Bottom Layer w10: v2(-3615,-410) -3566,-410 TP2.1@-3515,-461
A2: JP1.7 U5.26 | length 773
  Top Layer w10: JP1.7@-907,-97 -907,-301 -774.04,-433.96 -774.04,-748.43 -745.21,-777.26 U5.26@-719.5,-777.26
A3: JP1.6 U5.25 | length 685
  Top Layer w10: JP1.6@-807,-97 -807,-319 -719.5,-406.5 U5.25@-719.5,-745.76
A4: JP1.5 U5.24 | length 607.6
  Top Layer w10: JP1.5@-707,-97 -707,-370 -657.24,-419.76 U5.24@-657.24,-684
A5: JP1.4 U5.23 | length 594.8
  Top Layer w10: U5.23@-625.74,-684 -625.74,-129.23 -607,-110.49 JP1.4@-607,-97
ADC6: JP1.3 U5.22 | length 623.1
  Top Layer w10: U5.22@-594.24,-684 -594.24,-184.24 JP1.3@-507,-97
ADC7: JP1.2 U5.19 | length 681.1
  Top Layer w10: U5.19@-499.76,-684 -499.76,-644.39 -567,-577.14 -567,-257 JP1.2@-407,-97
BOOT0: JP7.3 R23.2 U8.21 | length 889.2
  Top Layer w10: JP7.3@-2161,-1395 -1942,-1176 -1942,-832 -1958.33,-815.67 -2000.76,-815.67 U8.21@-2002.91,-813.52 -2063.48,-813.52 -2072,-805 R23.2@-2072,-710.66
CS_TFT: JP4.3 U5.1 | length 668.3
  Top Layer w10: v2(-658,-982) -658,-1027.24 U5.1@-657.24,-1028
  Bottom Layer w10: v2(-658,-982) -559,-883 JP4.3@-77,-883
D10: JP1.1 U5.14 | length 808.6
  Top Layer w10: v2(-423,-809) -422.88,-808.88 -374.62,-808.88 U5.14@-374.5,-808.76
  Bottom Layer w10: v2(-423,-809) -423,-213 JP1.1@-307,-97
D_N: R12.2 U7.6 | length 124.2
  Top Layer w10: R12.2@-2721.8,-1011.56 -2720,-1009.76 U7.6@-2720,-888.09
D_P: R11.2 U7.5 | length 131.2
  Top Layer w10: R11.2@-2788.73,-1011.56 -2788.73,-930.14 -2770,-911.42 U7.5@-2770,-888.09
DC_TFT: JP4.4 U5.2 | length 721.1
  Top Layer w10: v2(-627,-910) -626.37,-910.63 -626.37,-1027.37 U5.2@-625.74,-1028
  Bottom Layer w10: v2(-627,-910) -578,-861 -155,-861 JP4.4@-77,-783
